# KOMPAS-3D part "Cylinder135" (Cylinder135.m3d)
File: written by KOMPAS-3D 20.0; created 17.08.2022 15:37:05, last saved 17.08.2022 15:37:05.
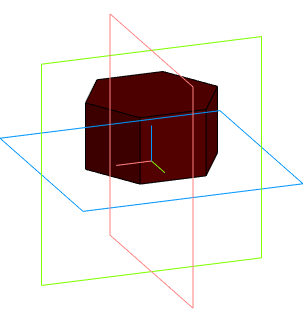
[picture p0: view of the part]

Document properties: Автор: artemsv220@gmail.com; Полное имя файла: \\192.168.2.25\новая общая папка\Медиа\Светильники\Кашпо\Кашпо и вазоны\DWG\Cylinder135.m3d

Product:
- Part/product: Cylinder135

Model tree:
1. Операция без истории:1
